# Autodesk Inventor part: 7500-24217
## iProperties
Shininess: 64.0
Length Units: 11269
Angle Units: 11279
Time Units: 11290
Mass Units: 11283
Length Display Precision: 3
Angle Display Precision: 2
Compacted: True
Company: SPI GmbH
Created: 2004-04
Part Number: 7500-24217
Material: Neutral
Document SubType Name: Blech
Designer: klemens
Manufacturer: Standard
Standards Organization: Custom
Description: FLACHSTECKER / 2,8-0,8
Cost Center: 0 kg
Authority: 46 mm^3
Density: 0.0
Volumn: 0.0
Area: 0.0
PropertySet Name: Model Information
Control State: 0
Master: False
Checked Out: False
SPI-MACHINE: Neutral
SPI-MATERIAL: Neutral
SPI-THICKNESS: 0.8000000000000002
SPI-USE-INCH: False
AIMD_MATERIAL: MS 63 CuZn37
AIMD_DESCRIPTION: DIN 46243
AIMD_PARTNO: Z403-F511128309
SaveDate: 2005-07-07
SaveTime: 17:07
TotalMass: 0 kg
TotalVolume: 46 mm^3
SM_Thickness: 0,8 mm
SM_Style: Neutral
SM_Extents: N/A
SM_Extents_Width: 0.000 mm
SM_Extents_Length: 0.000 mm
Author: klemens
Title: FLACHSTECKER / 2,8-0,8
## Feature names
1. Spiegeln1 [Mirror]
2. Eckenfase1
3. Fase1 [Chamfer]
4. Eckenfase2
5. Platte1
6. Platte2
7. Biegung1
8. Ausklinkung1
9. Ausklinkung2
10. Ausklinkung3
